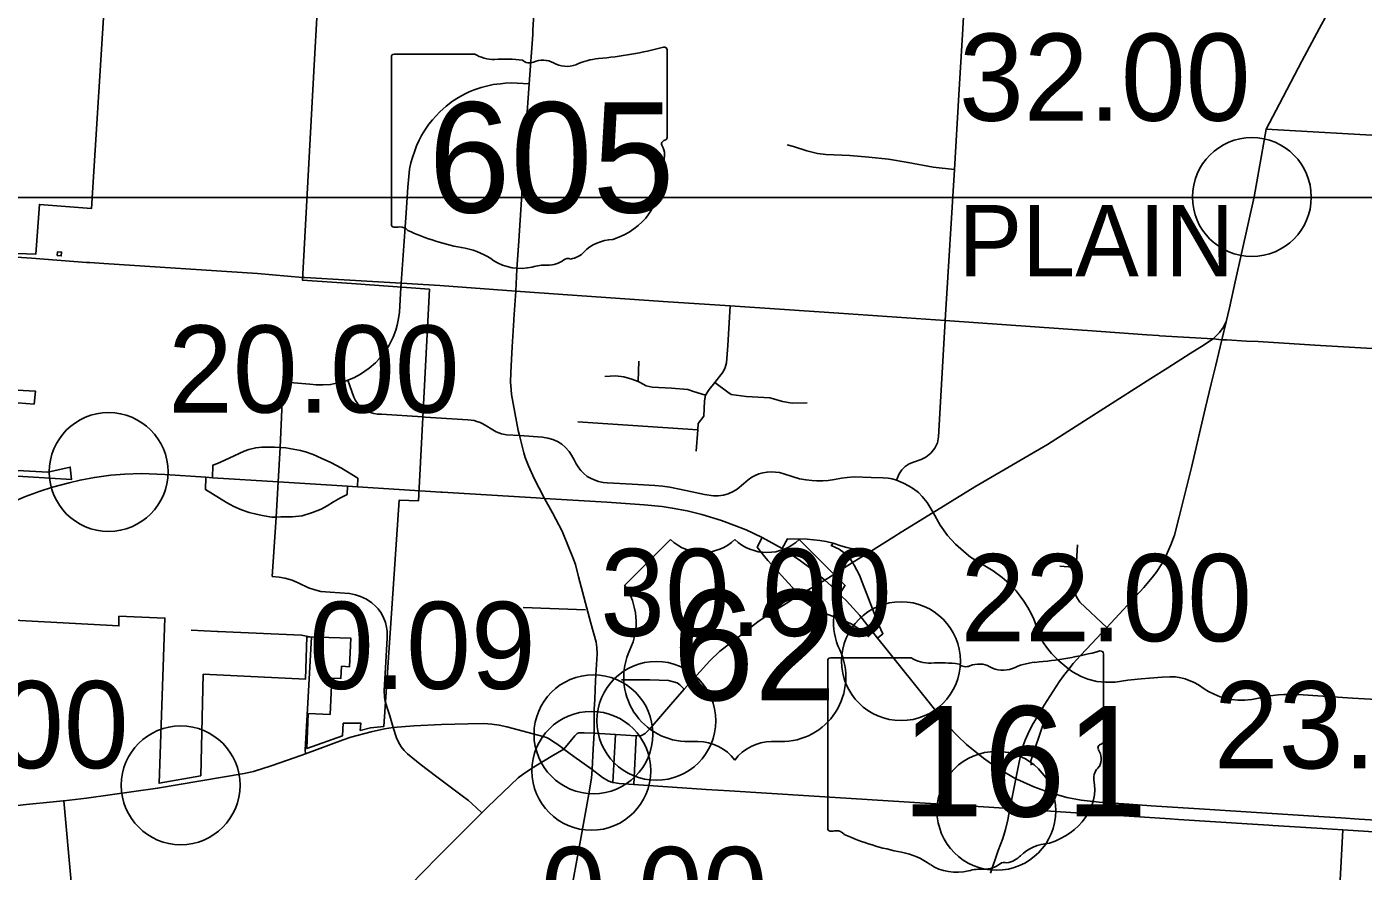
# Model space of a CAD drawing. Extents: x 1659811 to 1934326, y 644115 to 934867.
# Drawn here: x 1874937 to 1891809, y 756993 to 767651 of the extents above; entities that cross this region are included whole.
import ezdxf

# ---------------------------------------------------------------- set-up
doc = ezdxf.new("R2010")
doc.units = 0
for name, color, linetype in [('Default', 7, 'Continuous'), ('GM_X_City_Street', 7, 'Continuous'), ('GM_X_Corporation', 7, 'Continuous'), ('GM_X_County_Road', 7, 'Continuous'), ('GM_X_Interchange_Ramps', 7, 'Continuous'), ('GM_X_State_Route', 7, 'Continuous'), ('GM_X_State_Shield', 7, 'Continuous'), ('GM_X_Township_Road', 7, 'Continuous'), ('GM_X_Township_Text', 7, 'Continuous'), ('GM_X_US_Route', 7, 'Continuous'), ('GM_X_US_Shield', 7, 'Continuous'), ('SC_Scratch1', 7, 'Continuous')]:
    doc.layers.add(name, color=color, linetype=linetype)

msp = doc.modelspace()

# ---------------------------------------------------------------- linework, layer by layer
at = {"layer": 'Default'}
for centre in [(1890403, 765502), (1875971, 762032), (1885974, 759644), (1882885, 758891), (1882091, 758722), (1882065, 758261), (1876881, 758078), (1887178, 757756)]:
    msp.add_circle(centre, 750, dxfattribs=at)
at = {"layer": 'GM_X_City_Street'}
for points in [[(1879665, 764416), (1879710, 765065), (1879729, 765301), (1879750, 765625), (1879761, 765760), (1879771, 765853), (1879788, 765933), (1879805, 766001), (1879835, 766086), (1879859, 766149), (1879892, 766220), (1879921, 766279), (1879962, 766346), (1880013, 766422), (1880059, 766478), (1880153, 766579), (1880231, 766649), (1880311, 766710), (1880387, 766760), (1880463, 766799), (1880524, 766828), (1880587, 766854), (1880672, 766884), (1880760, 766907), (1880826, 766921), (1880916, 766932), (1880978, 766939), (1881052, 766943), (1881281, 766929)], [(1886648, 765849), (1886648, 765849), (1886705, 766792)], [(1884537, 766160), (1884616, 766141), (1884785, 766084), (1884921, 766050), (1885023, 766039), (1885329, 766028), (1885566, 766005), (1885815, 765982), (1886064, 765937), (1886381, 765880), (1886648, 765849)], [(1886535, 764015), (1886648, 765849)], [(1874061, 764793), (1874159, 764787), (1874329, 764774), (1874494, 764764), (1874997, 764730), (1875691, 764678), (1875732, 764675)], [(1875732, 764675), (1875910, 764665), (1877850, 764535), (1878419, 764488), (1878447, 764486)], [(1878447, 764486), (1879014, 764455), (1879665, 764416), (1880151, 764384), (1881111, 764314)], [(1878163, 762916), (1878174, 763071), (1878179, 763120), (1878188, 763150), (1878212, 763161), (1878309, 763158), (1878510, 763141), (1878589, 763133), (1878681, 763130), (1878773, 763136), (1878847, 763151), (1878925, 763167), (1878990, 763189), (1879067, 763222), (1879152, 763267), (1879262, 763344), (1879339, 763408), (1879385, 763461), (1879429, 763511), (1879473, 763570), (1879511, 763634), (1879563, 763735), (1879595, 763822), (1879613, 763886), (1879631, 763969), (1879641, 764050), (1879661, 764362)], [(1879661, 764362), (1879665, 764416)], [(1881111, 764314), (1881704, 764273), (1882972, 764185), (1883819, 764131), (1885188, 764036), (1886531, 763943), (1888019, 763839), (1888260, 763821), (1888327, 763816)], [(1883388, 762296), (1883407, 762564), (1883413, 762646), (1883485, 762737), (1883495, 762929), (1883506, 763001), (1883554, 763074), (1883625, 763162), (1883727, 763297), (1883754, 763352), (1883770, 763410), (1883786, 763630), (1883819, 764131)], [(1885918, 761930), (1885950, 762007), (1885986, 762058), (1886028, 762100), (1886076, 762133), (1886132, 762158), (1886227, 762188), (1886285, 762218), (1886350, 762269), (1886400, 762333), (1886433, 762402), (1886448, 762475), (1886480, 763064), (1886531, 763943), (1886535, 764015)], [(1888317, 759797), (1888574, 760070), (1889041, 760575), (1889145, 760702), (1889193, 760763), (1889266, 760875), (1889320, 760977), (1889350, 761047), (1889381, 761113), (1889426, 761236), (1889486, 761464), (1889640, 762089), (1889813, 762827), (1889891, 763144), (1889947, 763382), (1890022, 763700)], [(1890022, 763700), (1890022, 763700), (1890087, 763700), (1890335, 763685)], [(1890335, 763685), (1890482, 763677), (1891197, 763632), (1892213, 763572)], [(1882654, 763172), (1882663, 763430)], [(1878990, 763189), (1879042, 763047), (1879067, 762978), (1879088, 762936), (1879116, 762893), (1879150, 762856), (1879201, 762818), (1879242, 762796), (1879277, 762781), (1879318, 762769), (1879365, 762763), (1879414, 762760), (1879935, 762727), (1879968, 762725)], [(1882236, 763236), (1882368, 763246), (1882474, 763235), (1882575, 763205), (1882654, 763172), (1882679, 763162), (1882758, 763119), (1882834, 763104), (1883078, 763090), (1883282, 763071), (1883353, 763049), (1883506, 763001)], [(1883625, 763162), (1883787, 763038), (1883829, 763012), (1884019, 762985), (1884317, 762969), (1884364, 762956), (1884476, 762921), (1884598, 762901), (1884790, 762906)], [(1878138, 762343), (1878163, 762916)], [(1879968, 762725), (1880507, 762691), (1880546, 762687), (1880585, 762680), (1880617, 762671), (1880660, 762658), (1880686, 762644), (1880726, 762622), (1880821, 762562), (1880862, 762539), (1880895, 762525), (1880932, 762513), (1880992, 762502), (1881159, 762491), (1881448, 762470), (1881517, 762460), (1881579, 762441), (1881637, 762416), (1881691, 762384), (1881736, 762345), (1881784, 762289), (1881814, 762246), (1881846, 762184), (1881875, 762133), (1881905, 762086), (1881932, 762051), (1881967, 762016), (1882014, 761977), (1882053, 761952), (1882101, 761932), (1882156, 761912), (1882213, 761901), (1882265, 761897), (1882579, 761878), (1882864, 761862), (1882963, 761854), (1883055, 761839), (1883258, 761798), (1883492, 761750), (1883605, 761732), (1883665, 761731), (1883732, 761739), (1883790, 761755), (1883855, 761785), (1883904, 761815), (1883984, 761884), (1884044, 761934), (1884089, 761966), (1884134, 761989), (1884180, 762008), (1884230, 762021), (1884283, 762030), (1884345, 762034), (1884389, 762031), (1884440, 762024), (1884495, 762009), (1884599, 761974), (1884694, 761947), (1884775, 761933), (1884847, 761925), (1884906, 761919), (1884985, 761920), (1885053, 761926), (1885133, 761938), (1885222, 761954), (1885294, 761964), (1885381, 761969), (1885598, 761964), (1885747, 761960), (1885811, 761956), (1885864, 761946), (1885918, 761930), (1886007, 761891), (1886076, 761853), (1886131, 761820), (1886194, 761772), (1886242, 761724), (1886305, 761647), (1886379, 761520)], [(1881895, 762665), (1883407, 762564)], [(1878084, 761462), (1878113, 761906), (1878138, 762343)], [(1878036, 760713), (1878084, 761462)], [(1886379, 761520), (1886466, 761361), (1886562, 761229), (1886661, 761121), (1886797, 761005), (1886851, 760958), (1887030, 760848), (1887138, 760784), (1887251, 760702), (1887340, 760625), (1887427, 760531), (1887478, 760466), (1887525, 760400), (1887576, 760322), (1887620, 760238), (1887649, 760175), (1887729, 759955), (1887770, 759881), (1887821, 759805), (1887872, 759740), (1887966, 759647), (1888092, 759545)], [(1888203, 761114), (1888183, 760823), (1888168, 760556), (1888174, 760498), (1888194, 760449), (1888233, 760391), (1888574, 760070)], [(1887979, 760842), (1888148, 760830), (1888183, 760823)], [(1879471, 759112), (1879464, 759135), (1879453, 759190), (1879449, 759274), (1879466, 759560), (1879487, 759936), (1879487, 760024), (1879479, 760075), (1879465, 760133), (1879436, 760206), (1879406, 760259), (1879375, 760304), (1879342, 760340), (1879295, 760379), (1879227, 760427), (1879150, 760462), (1879086, 760482), (1879013, 760497), (1878766, 760517), (1878651, 760525), (1878576, 760544), (1878493, 760570), (1878372, 760627), (1878288, 760665), (1878196, 760691), (1878125, 760704), (1878036, 760713)], [(1881203, 760320), (1881991, 760292)], [(1877013, 760036), (1877343, 760021), (1877352, 760021)], [(1877352, 760021), (1878407, 759972), (1878533, 759946)], [(1878456, 758475), (1878452, 758525), (1878482, 759044), (1878533, 759946)], [(1887361, 757846), (1887425, 758159), (1887466, 758371), (1887505, 758547), (1887539, 758646), (1887573, 758725), (1887628, 758837), (1887717, 758980), (1887780, 759088), (1887969, 759385), (1888026, 759461), (1888092, 759545), (1888148, 759613), (1888239, 759714), (1888317, 759797)], [(1882444, 759407), (1882804, 759410), (1883040, 759399), (1883148, 759370), (1883183, 759346), (1883236, 759291)], [(1888092, 759545), (1888140, 759510), (1888249, 759452), (1888332, 759418), (1888447, 759389), (1888553, 759378), (1888679, 759379), (1888837, 759404), (1889005, 759421), (1889112, 759431), (1889269, 759442), (1889366, 759447), (1889438, 759445), (1889506, 759434), (1889561, 759420), (1889673, 759375), (1889731, 759344), (1889800, 759297), (1889857, 759261), (1889927, 759226), (1890003, 759195), (1890065, 759176), (1890146, 759159), (1890224, 759152), (1890312, 759152), (1890401, 759162), (1890529, 759188), (1890630, 759206), (1890741, 759220), (1890808, 759222), (1890902, 759225), (1890988, 759222), (1891674, 759179), (1892879, 759110)], [(1879562, 758807), (1879521, 758953), (1879494, 759029), (1879471, 759112)], [(1878931, 758651), (1879028, 758687), (1879287, 758754), (1879455, 758792), (1879562, 758807), (1879822, 758827), (1880172, 758844)], [(1880681, 757732), (1880558, 757847), (1880515, 757884), (1880434, 757947), (1880113, 758186), (1879902, 758343), (1879745, 758477), (1879703, 758515), (1879665, 758565), (1879629, 758622), (1879606, 758675), (1879562, 758807)], [(1880172, 758844), (1880174, 758844), (1880508, 758852), (1880708, 758856), (1880809, 758848), (1880903, 758837), (1880996, 758816), (1881142, 758779), (1881315, 758732)], [(1881315, 758732), (1881441, 758698), (1881497, 758682), (1881531, 758666), (1881589, 758628), (1881629, 758602), (1881691, 758555)], [(1882074, 758277), (1882074, 758277), (1882089, 758537), (1882099, 758734)], [(1875399, 757881), (1875406, 757881), (1875693, 757917), (1876589, 758040), (1877681, 758226), (1877801, 758254), (1878022, 758324), (1878327, 758429), (1878456, 758475), (1878931, 758651)], [(1882335, 758115), (1882371, 758720)], [(1882602, 758086), (1882630, 758704)], [(1881691, 758555), (1881716, 758535), (1881845, 758441), (1882074, 758277), (1882205, 758177), (1882276, 758134), (1882305, 758123), (1882335, 758115), (1882345, 758113)], [(1881920, 757341), (1882038, 757991), (1882054, 758096), (1882066, 758170), (1882074, 758277)], [(1882345, 758113), (1882389, 758104), (1882414, 758101), (1882602, 758086), (1883515, 758025)], [(1883515, 758025), (1883808, 758006), (1887349, 757783)], [(1872322, 757520), (1872584, 757551), (1873632, 757684), (1874173, 757746), (1874928, 757834), (1875273, 757868), (1875399, 757881)], [(1875691, 754791), (1875691, 754794), (1875677, 754834), (1875676, 754896), (1875666, 754962), (1875656, 755016), (1875651, 755061), (1875638, 755114), (1875635, 755163), (1875641, 755401), (1875618, 755795), (1875557, 756373), (1875500, 756861), (1875406, 757881)], [(1887103, 756969), (1887201, 757255), (1887260, 757407), (1887294, 757522), (1887322, 757641), (1887349, 757783), (1887361, 757846)], [(1887349, 757783), (1888438, 757713)], [(1888438, 757713), (1888853, 757687)], [(1888853, 757687), (1889372, 757654)], [(1889476, 757647), (1890410, 757587)], [(1890617, 757574), (1890669, 757571)], [(1890877, 757558), (1891292, 757531)], [(1881755, 756447), (1881874, 757087), (1881920, 757341)]]:
    msp.add_lwpolyline(points, dxfattribs=at)
at = {"layer": 'GM_X_Corporation'}
for points in [[(1874701, 764794), (1875051, 764779), (1875097, 765409), (1875756, 765359), (1876031, 769777)], [(1878604, 767840), (1878567, 767165), (1878418, 764455), (1879037, 764411), (1880021, 764338), (1879881, 761666), (1879639, 761678), (1879444, 758819), (1879278, 758804), (1879148, 758770), (1879153, 758864), (1878932, 758860), (1878924, 758703), (1878472, 758542), (1878492, 758986), (1878767, 758973), (1878788, 759432), (1878904, 759426), (1878911, 759580), (1879012, 759575), (1879029, 759933), (1878472, 759950), (1878456, 759416), (1877166, 759480), (1877134, 758199), (1876609, 758104), (1876682, 760188), (1876101, 760211), (1876101, 760089), (1874769, 760164)]]:
    msp.add_lwpolyline(points, dxfattribs=at)
for points in [[(1875322, 764763), (1875373, 764758), (1875377, 764808), (1875327, 764812)], [(1874294, 762732), (1874568, 762763), (1874797, 762751), (1874821, 762903), (1875031, 762890), (1875049, 763050), (1874261, 763093)], [(1874394, 762064), (1874405, 762004), (1875502, 761936), (1875486, 762095), (1875202, 762030), (1874509, 762069)]]:
    msp.add_lwpolyline(points, close=True, dxfattribs=at)
at = {"layer": 'GM_X_County_Road'}
for points in [[(1888327, 763816), (1889078, 763761), (1889226, 763753)], [(1890022, 763700), (1890077, 763927)], [(1889226, 763753), (1889240, 763752), (1889913, 763712)], [(1889913, 763712), (1890022, 763700)], [(1887619, 758330), (1887615, 758344), (1887613, 758387), (1887777, 758876), (1887779, 758913), (1887771, 758938), (1887751, 758962), (1887717, 758980)], [(1889372, 757654), (1889476, 757647)], [(1890410, 757587), (1890617, 757574)], [(1890669, 757571), (1890877, 757558)], [(1890890, 747320), (1890890, 747323), (1890931, 747885), (1890949, 748370), (1890978, 749335), (1891096, 750643), (1891349, 754421), (1891423, 755633), (1891501, 756560), (1891551, 757514)], [(1891292, 757531), (1891551, 757514), (1893306, 757404), (1893425, 757394), (1893891, 757364)]]:
    msp.add_lwpolyline(points, dxfattribs=at)
at = {"layer": 'GM_X_Interchange_Ramps'}
for points in [[(1878138, 762343), (1878066, 762347), (1877903, 762344), (1877828, 762338), (1877739, 762316), (1877683, 762296), (1877556, 762236), (1877436, 762183), (1877347, 762139), (1877285, 762117), (1877284, 761959)], [(1879114, 761846), (1879119, 761952), (1878912, 762080), (1878774, 762152), (1878656, 762208), (1878551, 762252), (1878455, 762286), (1878392, 762303), (1878208, 762336), (1878138, 762343)], [(1877197, 761965), (1877193, 761811), (1877459, 761646), (1877551, 761596), (1877647, 761553), (1877746, 761521), (1877818, 761505), (1877911, 761482), (1878032, 761463), (1878084, 761462)], [(1878084, 761462), (1878144, 761464), (1878288, 761467), (1878415, 761480), (1878544, 761519), (1878652, 761564), (1878729, 761606), (1878811, 761657), (1878898, 761705), (1878982, 761748), (1878987, 761854)], [(1884220, 761207), (1884160, 761084), (1884202, 761029), (1884294, 760916), (1884389, 760808), (1884465, 760727), (1884647, 760528), (1884681, 760472)], [(1885553, 761009), (1885527, 761051), (1885412, 761058), (1885348, 761066), (1885290, 761081), (1885215, 761102), (1885117, 761134), (1885029, 761153), (1884951, 761167), (1884868, 761177), (1884790, 761183), (1884540, 761188), (1884472, 761066)], [(1885363, 760891), (1885318, 760961), (1885257, 761011), (1885191, 761058), (1885093, 761103), (1885117, 761134)], [(1885678, 759935), (1885745, 759990), (1885695, 760098), (1885484, 760640), (1885448, 760729), (1885383, 760855), (1885363, 760891)], [(1884681, 760472), (1884711, 760433), (1884765, 760394), (1884851, 760331), (1884936, 760283), (1885028, 760241), (1885245, 760161), (1885344, 760115), (1885456, 760044), (1885563, 759955), (1885618, 760010)]]:
    msp.add_lwpolyline(points, dxfattribs=at)
at = {"layer": 'GM_X_State_Route'}
for points in [[(1881324, 767554), (1881328, 767607), (1881358, 768155), (1881361, 768238)], [(1881111, 764314), (1881125, 764593), (1881150, 764948), (1881252, 766514), (1881281, 766929), (1881324, 767554)], [(1881087, 763959), (1881111, 764314)], [(1881057, 763452), (1881067, 763610), (1881086, 763947), (1881087, 763959)], [(1881475, 761698), (1881405, 761826), (1881342, 761950), (1881270, 762108), (1881231, 762216), (1881213, 762273), (1881159, 762491), (1881142, 762556), (1881057, 763011), (1881051, 763075), (1881045, 763164), (1881047, 763288), (1881057, 763452)], [(1874034, 761315), (1874400, 761488), (1874766, 761657), (1874922, 761724), (1875108, 761792), (1875262, 761840), (1875473, 761897), (1875610, 761930), (1875791, 761963), (1875997, 761991), (1876175, 762006), (1876381, 762012), (1876681, 761999), (1877197, 761965), (1877284, 761959), (1878113, 761906), (1878987, 761854), (1879114, 761846), (1880163, 761777)], [(1880163, 761777), (1880182, 761776), (1881370, 761704)], [(1881370, 761704), (1881475, 761698), (1882262, 761651), (1882733, 761619), (1882960, 761595), (1883087, 761577), (1883275, 761541), (1883458, 761495), (1883706, 761420), (1884019, 761304), (1884220, 761207), (1884472, 761066), (1884704, 760912), (1884834, 760815), (1884933, 760734)], [(1881904, 760707), (1881863, 760863), (1881831, 760952), (1881785, 761066), (1881696, 761287), (1881574, 761517), (1881475, 761698)], [(1882133, 759816), (1882127, 759886), (1882057, 760124), (1881904, 760707)], [(1884933, 760734), (1885012, 760668), (1885130, 760561), (1885221, 760466), (1885286, 760404), (1885452, 760222), (1885618, 760010), (1885678, 759935), (1885754, 759843), (1886364, 759080), (1886567, 758825), (1886685, 758701), (1886799, 758594), (1887014, 758420), (1887181, 758302), (1887425, 758159)], [(1882107, 759167), (1882118, 759401), (1882140, 759736), (1882133, 759816)], [(1882099, 758734), (1882101, 759040), (1882107, 759167)], [(1887425, 758159), (1887473, 758138)], [(1887473, 758138), (1887652, 758059), (1887835, 757991), (1888067, 757925), (1888249, 757891), (1888476, 757865), (1888849, 757839)], [(1888849, 757839), (1889133, 757819), (1889803, 757778), (1891315, 757680)], [(1891315, 757680), (1891524, 757667)], [(1891524, 757667), (1891758, 757652), (1892259, 757623)]]:
    msp.add_lwpolyline(points, dxfattribs=at)
at = {"layer": 'GM_X_State_Shield'}
for p, q in [((1883020, 766254), (1883020, 767359)), ((1879540, 767270), (1879540, 765157)), ((1880593, 767307), (1879574, 767307)), ((1883020, 766254), (1883020, 766254)), ((1885049, 759650), (1885049, 757536)), ((1886102, 759686), (1885083, 759686)), ((1888529, 758633), (1888529, 759738)), ((1888529, 758633), (1888529, 758633))]:
    msp.add_line(p, q, dxfattribs=at)
for centre, major_axis, start_param, end_param in [((1881780, 770188), (3691, 0), 4.814394, 5.042369), ((1882982, 767364), (38.7, 0), 6.141152, 7.989035), ((1879580, 767275), (40.3, 0), 1.712693, 3.28349), ((1880836, 767552), (391, 0), 4.042523, 4.731795), ((1880966, 766120), (1404, 0), 1.404758, 1.657858), ((1881284, 767286), (113, 0), 3.836095, 5.185415), ((1881450, 767042), (235, 0), 0.950623, 2.079405), ((1881753, 767377), (282, 0), 4.081561, 5.145723), ((1882251, 766661), (743, 0), 1.699011, 2.107814), ((1883011, 766173), (60, 0), 1.883978, 3.671073), ((1882979, 766249), (41.5, 0), 5.05454, 6.418171), ((1882630, 766033), (360, 0), 5.934695, 6.695948), ((1883159, 765791), (262, 0), 2.387724, 3.262537), ((1881987, 765650), (923, 0), 5.101752, 6.440018), ((1879580, 765153), (40.7, 0), 3.00124, 4.508301), ((1879586, 765369), (310, 0), 4.665946, 4.897461), ((1879650, 765035), (112, 0), 0.519207, 1.627899), ((1881063, 766934), (2665, 0), 4.195997, 4.488961), ((1880268, 764208), (834, 0), 0.823519, 1.323587), ((1881736, 764952), (298, 0), 4.937069, 5.64225), ((1882376, 764564), (506, 0), 1.647645, 2.488434), ((1881170, 765025), (529, 0), 4.026481, 4.996735), ((1881476, 764294), (435, 0), 1.495662, 1.94098), ((1881515, 764867), (282, 0), 4.691044, 5.507374), ((1881770, 764662), (79.4, 0), 1.147584, 2.315152), ((1887289, 762567), (3691, 0), 4.814394, 5.042369), ((1888490, 759743), (38.7, 0), 6.141152, 7.989035), ((1885088, 759654), (40.3, 0), 1.712693, 3.28349), ((1886345, 759931), (391, 0), 4.042523, 4.731795), ((1886474, 758500), (1404, 0), 1.404758, 1.657858), ((1886793, 759665), (113, 0), 3.836095, 5.185415), ((1886959, 759421), (235, 0), 0.950623, 2.079405), ((1887262, 759756), (282, 0), 4.081561, 5.145723), ((1887760, 759041), (743, 0), 1.699011, 2.107814), ((1888520, 758552), (60, 0), 1.883978, 3.671073), ((1888488, 758629), (41.5, 0), 5.05454, 6.418171), ((1888139, 758412), (360, 0), 5.934695, 6.695948), ((1888668, 758170), (262, 0), 2.387724, 3.262537), ((1887496, 758030), (923, 0), 5.101752, 6.440018), ((1885089, 757532), (40.7, 0), 3.00124, 4.508301), ((1885095, 757748), (310, 0), 4.665946, 4.897461), ((1885158, 757415), (112, 0), 0.519207, 1.627899), ((1886572, 759313), (2665, 0), 4.195997, 4.488961), ((1885777, 756587), (834, 0), 0.823519, 1.323587), ((1887885, 756943), (506, 0), 1.647645, 2.488434), ((1886679, 757404), (529, 0), 4.026481, 4.996735), ((1887023, 757246), (282, 0), 4.691044, 5.507374), ((1887278, 757041), (79.4, 0), 1.147584, 2.315152), ((1887245, 757332), (298, 0), 4.937069, 5.64225), ((1886985, 756673), (435, 0), 1.495662, 1.94098)]:
    msp.add_ellipse(centre, major_axis=major_axis, ratio=0.8, start_param=start_param, end_param=end_param, dxfattribs=at)
at = {"layer": 'GM_X_Township_Road'}
for points in [[(1886705, 766792), (1886750, 767555), (1886850, 769340), (1886945, 770931), (1886981, 771591), (1887010, 772079), (1887174, 774834), (1887165, 774869), (1887135, 774898), (1887133, 774899)], [(1890584, 766357), (1893842, 766172)]]:
    msp.add_lwpolyline(points, dxfattribs=at)
at = {"layer": 'GM_X_US_Route'}
for points in [[(1890752, 766679), (1891033, 767215), (1891258, 767633), (1891448, 767988), (1891939, 768900), (1891995, 769008), (1892238, 769458), (1892242, 769476), (1892275, 769894), (1892301, 770323), (1892323, 770411), (1892348, 770477), (1892426, 770551), (1893210, 771367), (1893603, 771698), (1893929, 771992), (1893990, 772034), (1894050, 772066), (1894135, 772102), (1894659, 772333), (1894933, 772460), (1895161, 772565)], [(1890193, 764431), (1890430, 765504), (1890584, 766357), (1890752, 766679)], [(1889952, 763750), (1889996, 763794), (1890039, 763857), (1890077, 763927), (1890101, 764016), (1890121, 764104), (1890193, 764431)], [(1889344, 763348), (1889625, 763526), (1889799, 763638), (1889857, 763675), (1889913, 763712), (1889952, 763750)], [(1887539, 762214), (1887825, 762381), (1888335, 762706), (1889128, 763212), (1889344, 763348)], [(1886423, 761547), (1886907, 761844), (1887539, 762214)], [(1885944, 761252), (1886248, 761439)], [(1886248, 761439), (1886379, 761520), (1886423, 761547)], [(1885170, 760768), (1885363, 760891), (1885553, 761009), (1885915, 761235), (1885944, 761252)], [(1884075, 760070), (1884166, 760143), (1884326, 760252), (1884523, 760373), (1884681, 760472), (1885012, 760668), (1885170, 760768)], [(1883520, 759603), (1883562, 759650), (1883686, 759770), (1883963, 759981), (1884075, 760070)], [(1883070, 759098), (1883236, 759291), (1883520, 759603)], [(1882832, 758823), (1883070, 759098)], [(1881716, 758535), (1881856, 758704), (1881871, 758720), (1881884, 758730), (1881906, 758741), (1881972, 758742), (1882099, 758734), (1882371, 758720), (1882630, 758704), (1882699, 758706), (1882746, 758733), (1882810, 758797), (1882832, 758823)], [(1880757, 757805), (1881141, 758174), (1881205, 758217), (1881309, 758288), (1881557, 758441), (1881716, 758535)], [(1876171, 751557), (1876256, 751744), (1876325, 751910), (1876506, 752212), (1876807, 752667), (1876946, 752881), (1877196, 753260), (1877279, 753413), (1877324, 753507), (1877439, 753872), (1877494, 754090), (1877534, 754213), (1877567, 754283), (1877589, 754326), (1877657, 754437), (1878655, 755556), (1879084, 756067), (1879427, 756451), (1879564, 756594), (1879778, 756816), (1880124, 757173), (1880423, 757471), (1880681, 757732), (1880757, 757805)]]:
    msp.add_lwpolyline(points, dxfattribs=at)
at = {"layer": 'GM_X_US_Shield'}
for p, q in [((1883063, 761182), (1882483, 760601)), ((1885268, 760601), (1884688, 761182)), ((1883295, 758629), (1883411, 758629)), ((1884340, 758629), (1884456, 758629))]:
    msp.add_line(p, q, dxfattribs=at)
for centre, radius, start, end in [((1883470, 761596), 580, 225.573, 314.427), ((1884282, 761596), 580, 225.573, 314.427), ((1881818, 760136), 812, 334.5471, 35.0009), ((1885933, 760136), 812, 144.9991, 205.4529), ((1883286, 759441), 812, 154.8319, 270.6383), ((1884465, 759441), 812, 269.3617, 25.1681), ((1883411, 758049), 580, 36.8699, 90), ((1884340, 758049), 580, 90, 143.1301)]:
    msp.add_arc(centre, radius, start, end, dxfattribs=at)
at = {"layer": 'SC_Scratch1'}
msp.add_lwpolyline([(1729596, 899996), (1925846, 899996), (1925846, 765496), (1729596, 765496)], close=True, dxfattribs=at)

# ---------------------------------------------------------------- texts
at = {"layer": 'Default'}
for s, p in [('32.00', (1886705, 766465)), ('20.00', (1876721, 762782)), ('30.00', (1882176, 759962)), ('22.00', (1886724, 759896)), ('0.09', (1878500, 759294)), ('20.00', (1872543, 758294)), ('23.62', (1889923, 758291)), ('0.00', (1881427, 756199))]:
    msp.add_text(s, height=1100, dxfattribs=at).set_placement(p)
at = {"layer": 'GM_X_State_Shield'}
for s, p in [('605', (1880008, 765306)), ('161', (1885979, 757685))]:
    msp.add_text(s, height=1392.2, dxfattribs=at).set_placement(p)
at = {"layer": 'GM_X_Township_Text'}
msp.add_text('PLAIN', height=900, rotation=0, dxfattribs=at).set_placement((1886701, 764501))
at = {"layer": 'GM_X_US_Shield'}
msp.add_text('62', height=1392.2, dxfattribs=at).set_placement((1883087, 759151))

doc.saveas('drawing.dxf')
